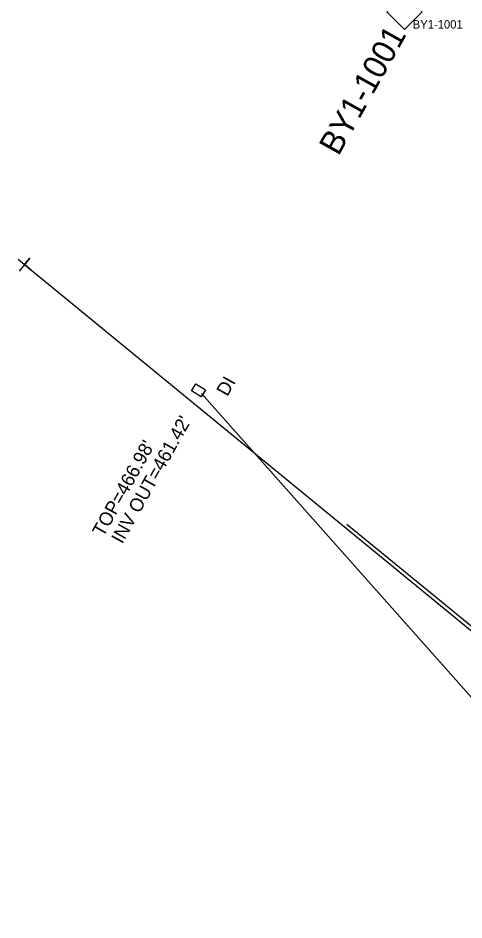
# Model space of a CAD drawing. Extents: x 2074109 to 2077820, y 741079 to 746031.
# Drawn here: x 2074600.8 to 2074733.4, y 743585.7 to 743853.8 of the extents above; entities that cross this region are included whole.
import ezdxf

# ---------------------------------------------------------------- set-up
doc = ezdxf.new("R2010")
doc.units = 0
for name, color, linetype in [('CTL Secondary Horizontal and Vertical CELL', 7, 'Continuous'), ('CTL Secondary Horizontal and Vertical Cogo Comment', 7, 'Continuous'), ('Exist Horizontal Baseline Alignment Station Label', 7, 'Continuous'), ('Exist Other Culture Fence Line', 7, 'Continuous'), ('Exist Property Corner CELL', 7, 'Continuous'), ('Exist Right of Way Line', 7, 'Continuous'), ('Exist Structure Minor Drop Inlet', 7, 'Continuous'), ('Exist Structure Minor Drop Inlet Text', 7, 'Continuous'), ('Exist Structure Minor Drop Inlet Top Elevation', 7, 'Continuous'), ('Exist Structure Minor Pipes RCP 30 Inch', 7, 'Continuous'), ('Exist Structure Minor Pipes RCP 30 Inch Invert', 7, 'Continuous')]:
    doc.layers.add(name, color=color, linetype=linetype)

msp = doc.modelspace()

# ---------------------------------------------------------------- linework, layer by layer
at = {"layer": 'CTL Secondary Horizontal and Vertical CELL'}
msp.add_lwpolyline([(2074710.41, 743855.69), (2074715.65, 743860.93), (2074720.9, 743855.68), (2074715.66, 743850.44)], close=True, dxfattribs=at)
at = {"layer": 'Exist Other Culture Fence Line'}
msp.add_lwpolyline([(2074698.56, 743703.34), (2074744.67, 743665.63), (2074791.41, 743627.23), (2074803.99, 743616.2), (2074885.32, 743455.46), (2074895.68, 743434.26), (2074905.46, 743413.47), (2074907.79, 743389.11), (2074904.61, 743348.97), (2074900.56, 743289.13), (2074907.07, 743242.98), (2074904.29, 743222.49), (2074892.12, 743176.94), (2074886.91, 743117.55), (2074880.07, 743050.36), (2074879.15, 743002.6)], dxfattribs=at)
at = {"layer": 'Exist Property Corner CELL'}
msp.add_line((2074602.77, 743780.53), (2074602.77, 743780.53), dxfattribs=at)
msp.add_lwpolyline([(2074600.85, 743782.12), (2074604.69, 743778.93), (2074602.77, 743780.53), (2074604.37, 743782.45), (2074601.17, 743778.6)], dxfattribs=at)
at = {"layer": 'Exist Right of Way Line'}
msp.add_line((2074602.77, 743780.53), (2074803.51, 743615.98), dxfattribs=at)
at = {"layer": 'Exist Structure Minor Drop Inlet'}
msp.add_lwpolyline([(2074653.68, 743745.1), (2074656.59, 743743.28), (2074655.29, 743741.19), (2074652.37, 743743.02)], close=True, dxfattribs=at)
at = {"layer": 'Exist Structure Minor Pipes RCP 30 Inch'}
msp.add_line((2074655.41, 743742.16), (2074919.07, 743445.14), dxfattribs=at)

# ---------------------------------------------------------------- texts
at = {"layer": 'CTL Secondary Horizontal and Vertical Cogo Comment'}
msp.add_text('BY1-1001', height=2.5, dxfattribs=at).set_placement((2074718.12, 743850.67))
at = {"layer": 'Exist Horizontal Baseline Alignment Station Label'}
msp.add_text('BY1-1001', height=7, rotation=60.742, dxfattribs=at).set_placement((2074696.06, 743812.57))
at = {"layer": 'Exist Structure Minor Drop Inlet Text'}
msp.add_text('DI', height=4, rotation=60.7411, dxfattribs=at).set_placement((2074663.06, 743741.12))
at = {"layer": 'Exist Structure Minor Drop Inlet Top Elevation'}
msp.add_text("TOP=466.98'", height=4, rotation=60.7411, dxfattribs=at).set_placement((2074626.18, 743699.35))
at = {"layer": 'Exist Structure Minor Pipes RCP 30 Inch Invert'}
msp.add_text("INV OUT=461.42'", height=4, rotation=60.7411, dxfattribs=at).set_placement((2074631.81, 743697.28))

doc.saveas('drawing.dxf')
